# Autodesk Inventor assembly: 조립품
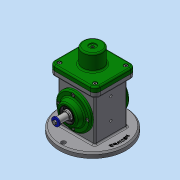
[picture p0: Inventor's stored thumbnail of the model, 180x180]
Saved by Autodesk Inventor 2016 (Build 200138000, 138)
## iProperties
Created: 2019-08
Part Number: 조립품
Material: 일반
Document SubType Name: Assembly
Designer: Administrator
Author: Administrator
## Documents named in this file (18)
- C:\Users\Administrator\Desktop\490804V1035\조립품.iam
- C:\Users\Administrator\Desktop\490804V1035\본체.ipt
- C:\Users\Administrator\Desktop\490804V1035\베어링 17 x 40 x 12.ipt
- C:\Users\Administrator\Desktop\490804V1035\편심축.ipt
- C:\Users\Administrator\Desktop\490804V1035\뒤커버.ipt
- C:\Users\Administrator\Desktop\490804V1035\앞커버.ipt
- C:\Users\Administrator\Desktop\490804V1035\오일 실 17 30 8.ipt
- C:\Users\Administrator\Desktop\490804V1035\키 4 x 4 x 12.ipt
- C:\Users\Administrator\Desktop\490804V1035\V-벨트풀리.ipt
- C:\Users\Administrator\Desktop\490804V1035\볼트 M4 x 10.ipt
- C:\Users\Administrator\Desktop\490804V1035\와셔 4x16.ipt
- C:\Users\Administrator\Desktop\490804V1035\링크.ipt
- C:\Users\Administrator\Desktop\490804V1035\슬라이더.ipt
- C:\Users\Administrator\Desktop\490804V1035\클레비스 핀 6 x 22.ipt
- 클레비스 핀 6 x 22.ipt
- C:\Users\Administrator\Desktop\490804V1035\E-링.ipt
- C:\Users\Administrator\Desktop\490804V1035\볼트 M4 x 8.ipt
- C:\Users\Administrator\Desktop\490804V1035\덮개.ipt
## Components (2 placed, 2 different names)
1. V-벨트풀리:1
2. E-링:1
